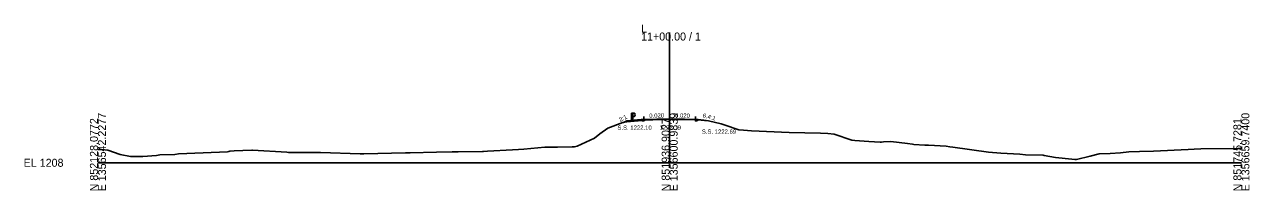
# Model space of a CAD drawing. Extents: x -26 to 3203, y -10 to 4066.
# Drawn here: x -25.7 to 402.8, y 490.3 to 548.4 of the extents above; entities that cross this region are included whole.
import ezdxf

# ---------------------------------------------------------------- set-up
doc = ezdxf.new("R2010")
doc.units = 0
for name, color, linetype in [('Exist Cross Section Cell', 7, 'Continuous'), ('Exist XS Center Line Elevation Label', 7, 'Continuous'), ('Exist XS Ground Line', 7, 'Continuous'), ('Prop XS Ditch Slope Text', 7, 'Continuous'), ('Prop XS Dump Level', 7, 'Continuous'), ('Prop XS Earthwork Shape', 7, 'Continuous'), ('Prop XS EOT Tick Mark', 7, 'Continuous'), ('Prop XS Finish Grade', 7, 'Continuous'), ('Prop XS Finish Grade Earthwork', 7, 'Continuous'), ('Prop XS Finish Grade Pavement', 7, 'Continuous'), ('Prop XS Guardrail', 7, 'Continuous'), ('Prop XS Pvmt Edge Slope', 7, 'Continuous'), ('Prop XS SE Text', 7, 'Continuous'), ('Prop XS Side Slope Text', 7, 'Continuous'), ('Prop XS SS Elevation Text', 7, 'Continuous'), ('Prop XS Subgrade Earthwork', 7, 'Continuous'), ('Prop XS Wedging', 7, 'Continuous')]:
    doc.layers.add(name, color=color, linetype=linetype)

msp = doc.modelspace()

# ---------------------------------------------------------------- linework, layer by layer
at = {"layer": 'Exist Cross Section Cell'}
for p, q in [((200, 500), (200, 545.56)), ((0, 500), (200, 500)), ((200, 500), (400, 500))]:
    msp.add_line(p, q, dxfattribs=at)
at = {"layer": 'Exist XS Ground Line'}
for p, q in [((183.64, 514.05), (184.3, 514.26)), ((184.3, 514.26), (185.01, 514.34)), ((185.01, 514.34), (191.38, 514.92)), ((191.38, 514.92), (196.9, 515.1)), ((196.9, 515.1), (199.89, 515.19)), ((199.89, 515.19), (205.15, 515.14)), ((205.15, 515.14), (208.6, 515.11)), ((208.6, 515.11), (212.24, 514.79)), ((212.24, 514.79), (213.58, 514.69)), ((213.58, 514.69), (217.99, 513.61)), ((173.76, 508.57), (175.55, 510.07)), ((175.55, 510.07), (178.33, 512.12)), ((178.33, 512.12), (183.64, 514.05)), ((217.99, 513.61), (219.11, 513.29)), ((219.11, 513.29), (224.25, 511.55)), ((224.25, 511.55), (225.82, 511.45)), ((225.82, 511.45), (228.66, 511.23)), ((228.66, 511.23), (241.85, 510.59)), ((241.85, 510.59), (252.78, 510.39)), ((252.78, 510.39), (255.28, 510.19)), ((255.28, 510.19), (257.49, 510)), ((257.49, 510), (263.77, 507.92)), ((166.74, 505.52), (167.61, 505.86)), ((167.61, 505.86), (173.76, 508.57)), ((263.77, 507.92), (264.81, 507.75)), ((264.81, 507.75), (269.73, 507.39)), ((269.73, 507.39), (273.67, 507.2)), ((273.67, 507.2), (274.14, 507.23)), ((274.14, 507.23), (274.83, 507.32)), ((274.83, 507.32), (277.42, 507.43)), ((277.42, 507.43), (283.19, 506.7)), ((283.19, 506.7), (284.98, 506.47)), ((284.98, 506.47), (285.45, 506.41)), ((285.45, 506.41), (289.24, 506.2)), ((289.24, 506.2), (290.55, 506.13)), ((290.55, 506.13), (296.7, 505.76)), ((296.7, 505.76), (297.99, 505.58)), ((0, 504.68), (1.26, 504.7)), ((1.26, 504.7), (3.47, 504.38)), ((3.47, 504.38), (7.81, 502.91)), ((7.81, 502.91), (11.41, 502.25)), ((11.41, 502.25), (15.69, 502.17)), ((15.69, 502.17), (20.43, 502.55)), ((20.43, 502.55), (21.7, 502.8)), ((21.7, 502.8), (26.87, 502.92)), ((26.87, 502.92), (28.23, 503.16)), ((28.23, 503.16), (36.8, 503.49)), ((36.8, 503.49), (45.34, 503.88)), ((45.34, 503.88), (45.73, 503.98)), ((45.73, 503.98), (46.14, 504.01)), ((46.14, 504.01), (47.68, 504.23)), ((47.68, 504.23), (50.63, 504.32)), ((50.63, 504.32), (53.78, 504.38)), ((53.78, 504.38), (54.1, 504.36)), ((54.1, 504.36), (66.1, 503.66)), ((66.1, 503.66), (66.64, 503.64)), ((66.64, 503.64), (76.13, 503.63)), ((76.13, 503.63), (77.9, 503.57)), ((77.9, 503.57), (91.77, 503.16)), ((91.77, 503.16), (93.05, 503.13)), ((93.05, 503.13), (107.56, 503.5)), ((107.56, 503.5), (109.18, 503.52)), ((109.18, 503.52), (118.46, 503.76)), ((118.46, 503.76), (123.97, 503.82)), ((123.97, 503.82), (126.07, 503.85)), ((126.07, 503.85), (134.55, 503.94)), ((134.55, 503.94), (134.91, 503.96)), ((134.91, 503.96), (136.27, 504.02)), ((136.27, 504.02), (145.04, 504.51)), ((145.04, 504.51), (147.13, 504.62)), ((147.13, 504.62), (149.04, 504.72)), ((149.04, 504.72), (156.32, 505.42)), ((156.32, 505.42), (160.8, 505.46)), ((160.8, 505.46), (165.87, 505.54)), ((165.87, 505.54), (166.74, 505.52)), ((297.99, 505.58), (299.06, 505.47)), ((299.06, 505.47), (311.48, 503.77)), ((311.48, 503.77), (315.88, 503.41)), ((315.88, 503.41), (322.48, 502.96)), ((322.48, 502.96), (324.44, 502.79)), ((324.44, 502.79), (330.61, 502.63)), ((330.61, 502.63), (330.99, 502.59)), ((330.99, 502.59), (334.93, 501.81)), ((334.93, 501.81), (340.69, 501.3)), ((342.31, 501.12), (347.07, 502.26)), ((347.07, 502.26), (350.27, 503.13)), ((350.27, 503.13), (354.05, 503.26)), ((354.05, 503.26), (357.71, 503.51)), ((357.71, 503.51), (360.68, 503.87)), ((360.68, 503.87), (364.38, 503.92)), ((364.38, 503.92), (369.26, 504.07)), ((369.26, 504.07), (381.36, 504.7)), ((381.36, 504.7), (383.5, 504.82)), ((383.5, 504.82), (385.79, 504.84)), ((385.79, 504.84), (398.92, 504.97)), ((398.92, 504.97), (400, 504.99)), ((340.69, 501.3), (341.69, 501.16)), ((341.69, 501.16), (342.31, 501.12))]:
    msp.add_line(p, q, dxfattribs=at)
at = {"layer": 'Prop XS Dump Level'}
for p, q in [((200, 515.36), (191, 515.18)), ((209, 515.18), (200, 515.36))]:
    msp.add_line(p, q, dxfattribs=at)
at = {"layer": 'Prop XS Earthwork Shape'}
for points in [[(190.26, 514.82), (189.98, 515.1), (184.99, 514.7), (183.8, 514.1), (184.3, 514.26), (185.01, 514.34)], [(190.26, 514.82), (191, 514.88), (191, 514.64), (190.45, 514.63)], [(209, 515.08), (209.92, 515), (209.55, 514.63), (209, 514.64)], [(209.92, 515), (212.24, 514.79), (213.58, 514.69), (212, 514.94), (210.02, 515.1)]]:
    msp.add_lwpolyline(points, close=True, dxfattribs=at)
at = {"layer": 'Prop XS EOT Tick Mark'}
for p, q in [((191, 515.18), (191, 516.18)), ((209, 515.18), (209, 516.18))]:
    msp.add_line(p, q, dxfattribs=at)
at = {"layer": 'Prop XS Finish Grade'}
for p, q in [((191, 515.18), (189.98, 515.1)), ((209, 515.18), (210.02, 515.1))]:
    msp.add_line(p, q, dxfattribs=at)
at = {"layer": 'Prop XS Finish Grade Earthwork'}
for p, q in [((184.99, 514.7), (183.8, 514.1)), ((189.98, 515.1), (184.99, 514.7)), ((210.02, 515.1), (212, 514.94)), ((212, 514.94), (213.58, 514.69))]:
    msp.add_line(p, q, dxfattribs=at)
at = {"layer": 'Prop XS Finish Grade Pavement'}
for p, q in [((191, 515.18), (200, 515.36)), ((200, 515.36), (209, 515.18))]:
    msp.add_line(p, q, dxfattribs=at)
at = {"layer": 'Prop XS Guardrail'}
for p, q in [((186.67, 514.83), (186.67, 517.33)), ((186.67, 517.33), (187.17, 517.33)), ((187.17, 517.33), (187.17, 514.83)), ((187.17, 517.33), (187.67, 517.33)), ((187.67, 516.2), (187.17, 516.2)), ((187.67, 517.33), (187.96, 517.13)), ((187.96, 517.01), (187.67, 516.81)), ((187.67, 516.81), (187.67, 516.72)), ((187.67, 516.72), (187.96, 516.52)), ((187.96, 516.4), (187.67, 516.2)), ((187.96, 517.13), (187.99, 517.07)), ((187.99, 517.07), (187.96, 517.01)), ((187.96, 516.52), (187.99, 516.46)), ((187.99, 516.46), (187.96, 516.4))]:
    msp.add_line(p, q, dxfattribs=at)
at = {"layer": 'Prop XS Pvmt Edge Slope'}
for p, q in [((191, 515.18), (190.45, 514.63)), ((209, 515.18), (209.55, 514.63))]:
    msp.add_line(p, q, dxfattribs=at)
at = {"layer": 'Prop XS Subgrade Earthwork'}
for p, q in [((190.45, 514.63), (189.98, 515.1)), ((191, 514.64), (190.45, 514.63)), ((191, 514.64), (191, 514.88)), ((209, 514.64), (209, 515.08)), ((209, 514.64), (209.55, 514.63)), ((209.55, 514.63), (210.02, 515.1))]:
    msp.add_line(p, q, dxfattribs=at)
at = {"layer": 'Prop XS Wedging'}
msp.add_lwpolyline([(191.38, 514.92), (191.38, 515.13), (196.9, 515.24), (199.89, 515.3), (200, 515.3), (205.15, 515.2), (208.6, 515.13), (208.6, 515.11), (205.15, 515.14), (200, 515.19), (199.89, 515.19), (196.9, 515.1)], close=True, dxfattribs=at)

# ---------------------------------------------------------------- texts
at = {"layer": 'Exist Cross Section Cell'}
for s, p in [('11+00.00 / 1', (190, 542.76)), ('L', (190, 545.56)), ('EL 1208', (-26, 498.6))]:
    msp.add_text(s, height=2.8, dxfattribs=at).set_placement(p)
for s, p in [('N 852128.0772', (0, 490)), ('E 1356542.2277', (2.8, 490)), ('N 851936.9027', (200, 490)), ('E 1356600.9839', (202.8, 490)), ('N 851745.7281', (400, 490)), ('E 1356659.7400', (402.8, 490))]:
    msp.add_text(s, height=2.8, rotation=90, dxfattribs=at).set_placement(p)
at = {"layer": 'Exist XS Center Line Elevation Label'}
msp.add_text('1223.19', height=1.5, dxfattribs=at).set_placement((196.46, 511.59))
at = {"layer": 'Prop XS Ditch Slope Text'}
msp.add_text('6.4:1', height=1.5, rotation=345.9638, dxfattribs=at).set_placement((211.43, 515.9))
at = {"layer": 'Prop XS Dump Level'}
for p in [(188, 514.9), (212, 514.9)]:
    msp.add_text('Case1', height=0.04, dxfattribs=at).set_placement(p)
at = {"layer": 'Prop XS SE Text'}
for rotation, p in [(1.1458, (192.88, 515.72)), (358.8542, (201.88, 515.82))]:
    msp.add_text('0.020', height=1.5, rotation=rotation, dxfattribs=at).set_placement(p)
at = {"layer": 'Prop XS Side Slope Text'}
msp.add_text('2:1', height=1.5, rotation=26.5651, dxfattribs=at).set_placement((182.72, 514.28))
at = {"layer": 'Prop XS SS Elevation Text'}
for s, p in [('S.S. 1222.10', (181.75, 511.54)), ('S.S. 1222.69', (211.27, 510.15))]:
    msp.add_text(s, height=1.5, dxfattribs=at).set_placement(p)

doc.saveas('drawing.dxf')
